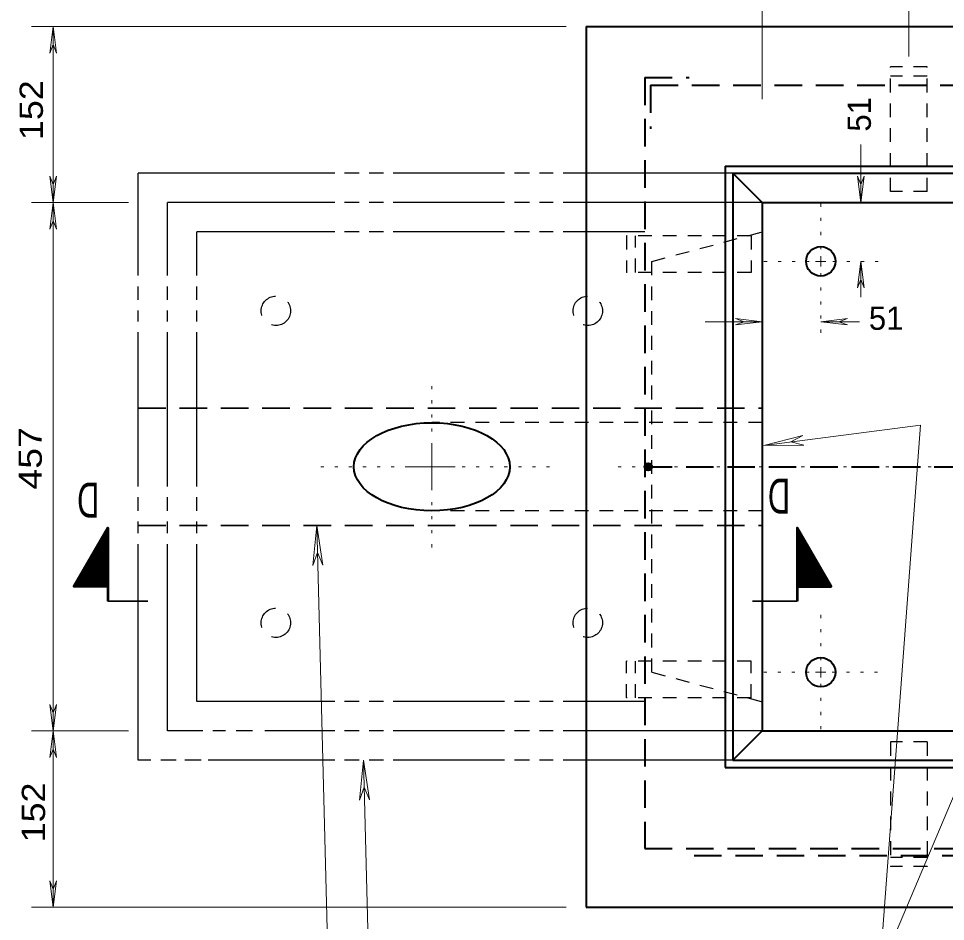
# Model space of a CAD drawing. Extents: x 312583 to 312854, y 144419 to 144597.
# Drawn here: x 312621.2 to 312651.47, y 144539.73 to 144569.21 of the extents above; entities that cross this region are included whole.
import ezdxf
from ezdxf.enums import TextEntityAlignment as Align

# ---------------------------------------------------------------- set-up
doc = ezdxf.new("R2010")
doc.units = 0
doc.header["$LTSCALE"] = 0.3
for name, pattern in [('DOTTED', [1.5, 0.3, -1.2]), ('MEDIUM_DASHED', [4.5, 3, -1.5]), ('SHORT_DASHED', [2.7, 1.5, -1.2])]:
    doc.linetypes.add(name, pattern=pattern)
doc.layers.add('1', color=7, linetype='Continuous', lineweight=25)
doc.layers.add('2', color=7, linetype='Continuous', lineweight=13)

msp = doc.modelspace()

# ---------------------------------------------------------------- linework, layer by layer
at = {"layer": '1', "lineweight": 40}
for p, q in [((312639.7337, 144568.9533), (312685.7337, 144568.9533)), ((312639.7337, 144568.9533), (312639.7337, 144540.2033)), ((312644.28, 144564.3993), (312644.28, 144544.7573)), ((312644.5254, 144564.1616), (312644.5254, 144544.995)), ((312644.5254, 144564.1616), (312645.4837, 144563.2033)), ((312645.4837, 144563.2033), (312666.659, 144563.2033)), ((312645.4837, 144545.9533), (312644.5254, 144544.995)), ((312645.4837, 144545.9533), (312644.5254, 144544.995)), ((312644.5254, 144544.995), (312680.942, 144544.995)), ((312644.28, 144544.7573), (312681.1797, 144544.7573)), ((312639.7337, 144540.2033), (312653.1504, 144540.2033))]:
    msp.add_line(p, q, dxfattribs=at)
at = {"layer": '1', "linetype": 'SHORT_DASHED'}
for p, q in [((312650.8734, 144567.6346), (312649.6774, 144567.6346)), ((312649.6774, 144563.5636), (312649.6774, 144567.6346)), ((312650.8734, 144563.5636), (312650.8734, 144567.6346)), ((312650.8734, 144567.3356), (312649.6774, 144567.3356)), ((312650.8734, 144563.5636), (312649.6774, 144563.5636)), ((312641.0524, 144562.1223), (312641.0524, 144560.9263)), ((312645.1234, 144562.1223), (312641.0524, 144562.1223)), ((312641.3514, 144560.9263), (312641.3514, 144562.1223)), ((312641.888, 144561.2866), (312645.4837, 144562.245)), ((312645.1234, 144562.1223), (312645.1234, 144560.9263)), ((312641.888, 144547.87), (312641.888, 144561.2866)), ((312645.1234, 144560.9263), (312641.0524, 144560.9263)), ((312645.4837, 144556.0196), (312634.7044, 144556.0196)), ((312645.4837, 144553.1446), (312634.6967, 144553.1446)), ((312641.0524, 144547.0343), (312641.0524, 144548.2303)), ((312645.1234, 144548.2303), (312641.0524, 144548.2303)), ((312641.3514, 144547.0343), (312641.3514, 144548.2303)), ((312645.1234, 144547.0343), (312645.1234, 144548.2303)), ((312641.888, 144547.87), (312645.4837, 144546.9116)), ((312645.1234, 144547.0343), (312641.0524, 144547.0343)), ((312650.8734, 144545.593), (312649.6774, 144545.593)), ((312649.6774, 144545.593), (312649.6774, 144541.5296)), ((312650.8734, 144545.593), (312650.8734, 144541.5296)), ((312650.8734, 144541.821), (312649.6774, 144541.821)), ((312650.8734, 144541.5296), (312649.6774, 144541.5296))]:
    msp.add_line(p, q, dxfattribs=at)
at = {"layer": '1', "linetype": 'MEDIUM_DASHED', "lineweight": 40}
for p, q in [((312641.6504, 144567.2896), (312641.6504, 144542.12)), ((312641.6504, 144567.2896), (312643.0994, 144567.2896)), ((312641.842, 144567.0366), (312641.842, 144565.6106)), ((312641.6504, 144554.5783), (312656.9837, 144554.5783)), ((312641.6504, 144542.12), (312683.817, 144542.12)), ((312643.2604, 144541.8823), (312655.067, 144541.8823))]:
    msp.add_line(p, q, dxfattribs=at)
at = {"layer": '1'}
for p, q in [((312631.5304, 144564.1616), (312625.1134, 144564.1616)), ((312625.1134, 144560.819), (312625.1134, 144564.1616)), ((312632.3277, 144564.1616), (312631.8524, 144564.1616)), ((312633.1174, 144564.1616), (312632.6497, 144564.1616)), ((312637.0734, 144564.1616), (312633.4394, 144564.1616)), ((312637.8937, 144564.1616), (312637.3954, 144564.1616)), ((312638.6604, 144564.1616), (312638.2157, 144564.1616)), ((312644.5254, 144564.1616), (312638.9824, 144564.1616)), ((312631.5304, 144563.2033), (312626.0717, 144563.2033)), ((312626.0717, 144560.819), (312626.0717, 144563.2033)), ((312632.3277, 144563.2033), (312631.8524, 144563.2033)), ((312633.1174, 144563.2033), (312632.6497, 144563.2033)), ((312637.0734, 144563.2033), (312633.4394, 144563.2033)), ((312637.8937, 144563.2033), (312637.3954, 144563.2033)), ((312638.6604, 144563.2033), (312638.2157, 144563.2033)), ((312645.4837, 144563.2033), (312638.9824, 144563.2033)), ((312631.5304, 144562.245), (312627.03, 144562.245)), ((312627.03, 144560.819), (312627.03, 144562.245)), ((312632.3277, 144562.245), (312631.8524, 144562.245)), ((312633.1174, 144562.245), (312632.6497, 144562.245)), ((312637.0734, 144562.245), (312633.4394, 144562.245)), ((312637.8937, 144562.245), (312637.3954, 144562.245)), ((312638.6604, 144562.245), (312638.2157, 144562.245)), ((312641.6504, 144562.245), (312638.9824, 144562.245)), ((312625.1134, 144560.0293), (312625.1134, 144560.4663)), ((312626.0717, 144560.0293), (312626.0717, 144560.4663)), ((312627.03, 144560.0293), (312627.03, 144560.4663)), ((312625.1134, 144559.324), (312625.1134, 144559.6766)), ((312626.0717, 144559.324), (312626.0717, 144559.6766)), ((312627.03, 144559.324), (312627.03, 144559.6766)), ((312625.1134, 144553.9343), (312625.1134, 144558.9713)), ((312626.0717, 144553.9343), (312626.0717, 144558.9713)), ((312627.03, 144553.9343), (312627.03, 144558.9713)), ((312625.1134, 144553.1446), (312625.1134, 144553.5816)), ((312626.0717, 144553.1446), (312626.0717, 144553.5816)), ((312627.03, 144553.1446), (312627.03, 144553.5816)), ((312625.1134, 144552.4086), (312625.1134, 144552.792)), ((312626.0717, 144552.4086), (312626.0717, 144552.792)), ((312627.03, 144552.4086), (312627.03, 144552.792)), ((312625.1134, 144544.995), (312625.1134, 144552.056)), ((312626.0717, 144545.9533), (312626.0717, 144552.056)), ((312627.03, 144546.9116), (312627.03, 144552.056)), ((312631.5304, 144546.9116), (312627.03, 144546.9116)), ((312632.3277, 144546.9116), (312631.8524, 144546.9116)), ((312633.1174, 144546.9116), (312632.6497, 144546.9116)), ((312637.0734, 144546.9116), (312633.4394, 144546.9116)), ((312637.8937, 144546.9116), (312637.3954, 144546.9116)), ((312638.6604, 144546.9116), (312638.2157, 144546.9116)), ((312641.6504, 144546.9116), (312638.9824, 144546.9116)), ((312627.2217, 144545.9533), (312626.0717, 144545.9533)), ((312627.9577, 144545.9533), (312627.5437, 144545.9533)), ((312628.8394, 144545.9533), (312628.3104, 144545.9533)), ((312631.5304, 144545.9533), (312629.2457, 144545.9533)), ((312632.3277, 144545.9533), (312631.8524, 144545.9533)), ((312633.1174, 144545.9533), (312632.6497, 144545.9533)), ((312637.0734, 144545.9533), (312633.4394, 144545.9533)), ((312637.8937, 144545.9533), (312637.3954, 144545.9533)), ((312638.6604, 144545.9533), (312638.2157, 144545.9533)), ((312645.4837, 144545.9533), (312638.9824, 144545.9533)), ((312625.5274, 144544.995), (312625.1134, 144544.995)), ((312626.3477, 144544.995), (312625.8494, 144544.995)), ((312627.168, 144544.995), (312626.639, 144544.995)), ((312631.5304, 144544.995), (312627.398, 144544.995)), ((312632.3277, 144544.995), (312631.8524, 144544.995)), ((312633.1174, 144544.995), (312632.6497, 144544.995)), ((312637.0734, 144544.995), (312633.4394, 144544.995)), ((312637.8937, 144544.995), (312637.3954, 144544.995)), ((312638.6604, 144544.995), (312638.2157, 144544.995)), ((312644.5254, 144544.995), (312638.9824, 144544.995))]:
    msp.add_line(p, q, dxfattribs=at)
at = {"layer": '1', "linetype": 'DOTTED', "lineweight": 13}
for p, q in [((312634.6967, 144555.7283), (312634.6967, 144557.5376)), ((312633.93, 144554.5783), (312630.8557, 144554.5783)), ((312638.5454, 144554.5783), (312635.4634, 144554.5783)), ((312634.6967, 144553.4283), (312634.6967, 144551.6266))]:
    msp.add_line(p, q, dxfattribs=at)
at = {"layer": '1', "linetype": 'MEDIUM_DASHED', "lineweight": 35}
for p, q in [((312625.1134, 144556.495), (312645.4837, 144556.495)), ((312625.1134, 144552.6616), (312645.4837, 144552.6616))]:
    msp.add_line(p, q, dxfattribs=at)
at = {"layer": '1', "lineweight": 13}
for q in [(312634.6967, 144555.345), (312633.93, 144554.5783), (312634.6967, 144553.8116), (312635.4634, 144554.5783)]:
    msp.add_line((312634.6967, 144554.5783), q, dxfattribs=at)
at = {"layer": '1', "lineweight": 35}
for p, q in [((312624.1244, 144552.3396), (312624.017, 144552.4086)), ((312624.1244, 144552.3703), (312624.0324, 144552.424)), ((312624.1244, 144552.401), (312624.04, 144552.447)), ((312624.1244, 144552.4316), (312624.0554, 144552.47)), ((312624.1244, 144552.4546), (312624.063, 144552.4853)), ((312624.1244, 144552.4853), (312624.0784, 144552.5083)), ((312624.1244, 144552.5083), (312624.086, 144552.5313)), ((312624.1244, 144552.539), (312624.1014, 144552.5466)), ((312624.1244, 144552.5696), (312624.109, 144552.5696)), ((312646.626, 144552.5696), (312646.6414, 144552.5696)), ((312646.626, 144552.539), (312646.649, 144552.5466)), ((312646.626, 144552.5083), (312646.6644, 144552.5313)), ((312646.626, 144552.4853), (312646.672, 144552.5083)), ((312646.626, 144552.4546), (312646.6874, 144552.4853)), ((312646.626, 144552.4316), (312646.695, 144552.47)), ((312646.626, 144552.401), (312646.7104, 144552.447)), ((312646.626, 144552.3703), (312646.718, 144552.424)), ((312646.626, 144552.3396), (312646.7334, 144552.4086)), ((312624.1244, 144551.9333), (312623.8407, 144552.0943)), ((312624.1244, 144551.9563), (312623.8484, 144552.1096)), ((312624.1244, 144551.987), (312623.8637, 144552.1403)), ((312624.1244, 144552.01), (312623.8714, 144552.1556)), ((312624.1244, 144552.0406), (312623.8867, 144552.1786)), ((312624.1244, 144552.0713), (312623.8944, 144552.2016)), ((312624.1244, 144552.0943), (312623.9097, 144552.217)), ((312624.1244, 144552.125), (312623.9174, 144552.24)), ((312624.1244, 144552.148), (312623.9327, 144552.263)), ((312624.1244, 144552.1786), (312623.948, 144552.2783)), ((312624.1244, 144552.2093), (312623.9557, 144552.3013)), ((312624.1244, 144552.24), (312623.971, 144552.3243)), ((312624.1244, 144552.263), (312623.9864, 144552.3396)), ((312624.1244, 144552.2936), (312623.994, 144552.3626)), ((312624.1244, 144552.3166), (312624.0094, 144552.3856)), ((312646.626, 144552.3166), (312646.741, 144552.3856)), ((312646.626, 144552.2936), (312646.7564, 144552.3626)), ((312646.626, 144552.263), (312646.764, 144552.3396)), ((312646.626, 144552.24), (312646.7794, 144552.3243)), ((312646.626, 144552.2093), (312646.7947, 144552.3013)), ((312646.626, 144552.1786), (312646.8024, 144552.2783)), ((312646.626, 144552.148), (312646.8177, 144552.263)), ((312646.626, 144552.125), (312646.833, 144552.24)), ((312646.626, 144552.0943), (312646.8407, 144552.217)), ((312646.626, 144552.0713), (312646.856, 144552.2016)), ((312646.626, 144552.0406), (312646.8637, 144552.1786)), ((312646.626, 144552.01), (312646.879, 144552.1556)), ((312646.626, 144551.987), (312646.8867, 144552.1403)), ((312646.626, 144551.9563), (312646.902, 144552.1096)), ((312646.626, 144551.9333), (312646.9097, 144552.0943)), ((312624.1244, 144551.5423), (312623.672, 144551.803)), ((312624.1244, 144551.573), (312623.6797, 144551.826)), ((312624.1244, 144551.6036), (312623.695, 144551.8413)), ((312624.1244, 144551.6266), (312623.7027, 144551.8643)), ((312624.1244, 144551.6496), (312623.718, 144551.8873)), ((312624.1244, 144551.6803), (312623.7257, 144551.9103)), ((312624.1244, 144551.711), (312623.741, 144551.9256)), ((312624.1244, 144551.7416), (312623.7564, 144551.9486)), ((312624.1244, 144551.7646), (312623.764, 144551.9716)), ((312624.1244, 144551.7953), (312623.7794, 144551.987)), ((312624.1244, 144551.8183), (312623.7947, 144552.01)), ((312624.1244, 144551.849), (312623.8024, 144552.033)), ((312624.1244, 144551.872), (312623.8177, 144552.0483)), ((312624.1244, 144551.9026), (312623.8254, 144552.0713)), ((312646.626, 144551.9026), (312646.925, 144552.0713)), ((312646.626, 144551.872), (312646.9327, 144552.0483)), ((312646.626, 144551.849), (312646.948, 144552.033)), ((312646.626, 144551.8183), (312646.9557, 144552.01)), ((312646.626, 144551.7953), (312646.971, 144551.987)), ((312646.626, 144551.7646), (312646.9864, 144551.9716)), ((312646.626, 144551.7416), (312646.994, 144551.9486)), ((312646.626, 144551.711), (312647.0094, 144551.9256)), ((312646.626, 144551.6803), (312647.0247, 144551.9103)), ((312646.626, 144551.6496), (312647.0324, 144551.8873)), ((312646.626, 144551.6266), (312647.0477, 144551.8643)), ((312646.626, 144551.6036), (312647.0554, 144551.8413)), ((312646.626, 144551.573), (312647.0707, 144551.826)), ((312646.626, 144551.5423), (312647.0784, 144551.803)), ((312624.1244, 144551.1283), (312623.4957, 144551.4886)), ((312624.1244, 144551.1513), (312623.5034, 144551.5116)), ((312624.1244, 144551.182), (312623.5187, 144551.5346)), ((312624.1244, 144551.2126), (312623.5264, 144551.55)), ((312624.1244, 144551.2433), (312623.5417, 144551.573)), ((312624.1244, 144551.2663), (312623.5494, 144551.596)), ((312624.1244, 144551.297), (312623.5647, 144551.6113)), ((312624.1167, 144551.32), (312623.5724, 144551.642)), ((312624.1244, 144551.3506), (312623.5877, 144551.6573)), ((312624.1244, 144551.3736), (312623.603, 144551.6803)), ((312624.1244, 144551.4043), (312623.6107, 144551.7033)), ((312624.1244, 144551.435), (312623.626, 144551.7186)), ((312624.1244, 144551.458), (312623.6337, 144551.7416)), ((312624.1244, 144551.4886), (312623.649, 144551.7646)), ((312624.1244, 144551.5193), (312623.6567, 144551.78)), ((312646.626, 144551.5193), (312647.0937, 144551.78)), ((312646.626, 144551.4886), (312647.1014, 144551.7646)), ((312646.626, 144551.458), (312647.1167, 144551.7416)), ((312646.626, 144551.435), (312647.1244, 144551.7186)), ((312646.626, 144551.4043), (312647.1397, 144551.7033)), ((312646.626, 144551.3736), (312647.1474, 144551.6803)), ((312646.626, 144551.3506), (312647.1627, 144551.6573)), ((312646.626, 144551.297), (312647.1857, 144551.6113)), ((312646.626, 144551.2663), (312647.201, 144551.596)), ((312646.626, 144551.2433), (312647.2087, 144551.573)), ((312646.626, 144551.2126), (312647.224, 144551.55)), ((312646.626, 144551.182), (312647.2317, 144551.5346)), ((312646.626, 144551.1513), (312647.247, 144551.5116)), ((312646.626, 144551.1283), (312647.2547, 144551.4886)), ((312646.6337, 144551.32), (312647.178, 144551.642)), ((312624.1244, 144550.7143), (312623.3117, 144551.182)), ((312624.1244, 144550.745), (312623.327, 144551.205)), ((312624.1244, 144550.768), (312623.3347, 144551.2203)), ((312624.1244, 144550.7986), (312623.35, 144551.2433)), ((312624.1167, 144550.8216), (312623.3577, 144551.2663)), ((312624.1167, 144550.8523), (312623.373, 144551.2816)), ((312624.1244, 144550.8753), (312623.3807, 144551.3046)), ((312624.1244, 144550.906), (312623.396, 144551.3276)), ((312624.1244, 144550.9366), (312623.4114, 144551.343)), ((312624.1244, 144550.9596), (312623.419, 144551.366)), ((312624.1244, 144550.9903), (312623.4344, 144551.389)), ((312624.1244, 144551.021), (312623.4497, 144551.412)), ((312624.1244, 144551.044), (312623.4574, 144551.4273)), ((312624.1167, 144551.0746), (312623.4727, 144551.4503)), ((312624.1244, 144551.1053), (312623.4804, 144551.4733)), ((312646.626, 144551.1053), (312647.27, 144551.4733)), ((312646.626, 144551.044), (312647.293, 144551.4273)), ((312646.626, 144551.021), (312647.3007, 144551.412)), ((312646.626, 144550.9903), (312647.316, 144551.389)), ((312646.626, 144550.9596), (312647.3314, 144551.366)), ((312646.626, 144550.9366), (312647.339, 144551.343)), ((312646.626, 144550.906), (312647.3544, 144551.3276)), ((312646.626, 144550.8753), (312647.3697, 144551.3046)), ((312646.626, 144550.7986), (312647.4004, 144551.2433)), ((312646.626, 144550.768), (312647.4157, 144551.2203)), ((312646.626, 144550.745), (312647.4234, 144551.205)), ((312646.626, 144550.7143), (312647.4387, 144551.182)), ((312646.6337, 144551.0746), (312647.2777, 144551.4503)), ((312646.6337, 144550.8523), (312647.3774, 144551.2816)), ((312646.6337, 144550.8216), (312647.3927, 144551.2663)), ((312623.4727, 144550.6683), (312623.1354, 144550.8753)), ((312623.5264, 144550.6683), (312623.143, 144550.8906)), ((312623.5724, 144550.6683), (312623.1584, 144550.9136)), ((312623.6184, 144550.6683), (312623.166, 144550.9366)), ((312623.672, 144550.6683), (312623.1814, 144550.952)), ((312623.718, 144550.6683), (312623.189, 144550.975)), ((312623.764, 144550.6683), (312623.2044, 144550.9903)), ((312623.8177, 144550.6683), (312623.2197, 144551.0133)), ((312623.8637, 144550.6683), (312623.2274, 144551.0363)), ((312623.9097, 144550.6683), (312623.2427, 144551.0516)), ((312623.9557, 144550.6683), (312623.258, 144551.0746)), ((312624.0094, 144550.6683), (312623.2657, 144551.0976)), ((312624.0477, 144550.6683), (312623.281, 144551.113)), ((312624.1014, 144550.6683), (312623.2887, 144551.1436)), ((312624.1244, 144550.6836), (312623.304, 144551.159)), ((312646.626, 144550.6836), (312647.4464, 144551.159)), ((312646.649, 144550.6683), (312647.4617, 144551.1436)), ((312646.7027, 144550.6683), (312647.4694, 144551.113)), ((312646.741, 144550.6683), (312647.4847, 144551.0976)), ((312646.7947, 144550.6683), (312647.4924, 144551.0746)), ((312646.8407, 144550.6683), (312647.5077, 144551.0516)), ((312646.8867, 144550.6683), (312647.523, 144551.0363)), ((312646.9327, 144550.6683), (312647.5307, 144551.0133)), ((312646.9864, 144550.6683), (312647.546, 144550.9903)), ((312647.0324, 144550.6683), (312647.5614, 144550.975)), ((312647.0784, 144550.6683), (312647.569, 144550.952)), ((312647.132, 144550.6683), (312647.5844, 144550.9366)), ((312647.178, 144550.6683), (312647.592, 144550.9136)), ((312647.224, 144550.6683), (312647.6074, 144550.8906)), ((312647.2777, 144550.6683), (312647.615, 144550.8753)), ((312623.0434, 144550.6683), (312623.028, 144550.6836)), ((312623.0894, 144550.6683), (312623.0357, 144550.7066)), ((312623.143, 144550.6683), (312623.051, 144550.722)), ((312623.189, 144550.6683), (312623.0664, 144550.745)), ((312623.2427, 144550.6683), (312623.074, 144550.768)), ((312623.281, 144550.6683), (312623.0894, 144550.7833)), ((312623.3347, 144550.6683), (312623.097, 144550.8063)), ((312623.3807, 144550.6683), (312623.1124, 144550.8293)), ((312623.4267, 144550.6683), (312623.12, 144550.8446)), ((312647.3237, 144550.6683), (312647.6304, 144550.8446)), ((312647.3697, 144550.6683), (312647.638, 144550.8293)), ((312647.4157, 144550.6683), (312647.6534, 144550.8063)), ((312647.4694, 144550.6683), (312647.661, 144550.7833)), ((312647.5077, 144550.6683), (312647.6764, 144550.768)), ((312647.5614, 144550.6683), (312647.684, 144550.745)), ((312647.6074, 144550.6683), (312647.6994, 144550.722)), ((312647.661, 144550.6683), (312647.7147, 144550.7066)), ((312647.707, 144550.6683), (312647.7224, 144550.6836)), ((312624.1244, 144550.193), (312625.4277, 144550.193)), ((312645.1694, 144550.193), (312646.626, 144550.193))]:
    msp.add_line(p, q, dxfattribs=at)
at = {"layer": '1', "lineweight": 53}
for p, q in [((312624.1244, 144550.6683), (312624.1244, 144550.193)), ((312646.626, 144550.6683), (312646.626, 144550.193))]:
    msp.add_line(p, q, dxfattribs=at)
at = {"layer": '1', "linetype": 'MEDIUM_DASHED', "lineweight": 40}
msp.add_lwpolyline([(312641.842, 144567.0366), (312683.817, 144567.0366), (312683.817, 144542.12)], dxfattribs=at)
at = {"layer": '1', "lineweight": 40}
for points in [[(312644.28, 144564.3993), (312681.1797, 144564.3993), (312681.1797, 144544.7573)], [(312644.5254, 144564.1616), (312680.942, 144564.1616), (312680.942, 144544.995)], [(312645.4837, 144563.2033), (312645.4837, 144545.9533), (312679.9837, 144545.9533)]]:
    msp.add_lwpolyline(points, dxfattribs=at)
at = {"layer": '1', "lineweight": 53}
for points in [[(312624.1244, 144550.6683), (312623.0127, 144550.6683), (312624.1244, 144552.585)], [(312646.626, 144550.6683), (312647.7377, 144550.6683), (312646.626, 144552.585)]]:
    msp.add_lwpolyline(points, close=True, dxfattribs=at)
at = {"layer": '1', "lineweight": 40}
for centre, radius in [((312647.3975, 144561.2866), 0.4792), ((312641.7673, 144554.5783), 0.1198), ((312641.7673, 144554.5783), 0.0838), ((312641.7673, 144554.5783), 0.0587), ((312647.3975, 144547.87), 0.4792)]:
    msp.add_circle(centre, radius, dxfattribs=at)
at = {"layer": '1', "linetype": 'MEDIUM_DASHED'}
for centre in [(312629.6079, 144559.6699), (312639.7912, 144559.6699), (312629.6079, 144549.4867), (312639.7912, 144549.4867)]:
    msp.add_circle(centre, 0.4792, dxfattribs=at)
at = {"layer": '1', "lineweight": 40}
msp.add_ellipse((312634.7001, 144554.5783), major_axis=(-2.5458, 0), ratio=0.564653, dxfattribs=at)
at = {"layer": '2'}
for p, q in [((312645.4837, 144566.5843), (312645.4837, 144572.0813)), ((312650.2754, 144567.972), (312650.2754, 144572.0813)), ((312639.082, 144568.9533), (312621.6327, 144568.9533)), ((312622.338, 144568.9533), (312622.2307, 144568.087)), ((312622.338, 144568.9533), (312622.4454, 144568.087)), ((312622.2307, 144568.087), (312622.338, 144568.363)), ((312622.4454, 144568.087), (312622.338, 144568.363)), ((312648.7037, 144563.2033), (312648.7037, 144565.097)), ((312622.2307, 144564.0696), (312622.338, 144563.7936)), ((312622.338, 144563.2033), (312622.2307, 144564.0696)), ((312622.4454, 144564.0696), (312622.338, 144563.7936)), ((312622.338, 144563.2033), (312622.4454, 144564.0696)), ((312648.5964, 144564.0696), (312648.7037, 144563.7936)), ((312648.7037, 144563.2033), (312648.5964, 144564.0696)), ((312648.811, 144564.0696), (312648.7037, 144563.7936)), ((312648.7037, 144563.2033), (312648.811, 144564.0696)), ((312624.7914, 144563.2033), (312621.6327, 144563.2033)), ((312622.338, 144563.2033), (312622.2307, 144562.337)), ((312622.338, 144563.2033), (312622.4454, 144562.337)), ((312659.9354, 144563.2033), (312649.317, 144538.118)), ((312622.2307, 144562.337), (312622.338, 144562.613)), ((312622.4454, 144562.337), (312622.338, 144562.613)), ((312647.4004, 144561.2866), (312647.224, 144561.2866)), ((312647.4004, 144561.2866), (312647.4004, 144561.4553)), ((312647.4004, 144561.2866), (312647.569, 144561.2866)), ((312647.4004, 144561.2866), (312647.4004, 144561.118)), ((312648.7037, 144561.2866), (312648.5964, 144560.4203)), ((312648.7037, 144560.1136), (312648.7037, 144561.2866)), ((312648.7037, 144561.2866), (312648.811, 144560.4203)), ((312648.5964, 144560.4203), (312648.7037, 144560.6963)), ((312648.811, 144560.4203), (312648.7037, 144560.6963)), ((312644.6174, 144559.4236), (312644.8934, 144559.3163)), ((312645.4837, 144559.3163), (312644.6174, 144559.4236)), ((312647.4004, 144559.3163), (312648.2667, 144559.4236)), ((312648.2667, 144559.4236), (312647.9907, 144559.3163)), ((312643.6207, 144559.3163), (312645.4837, 144559.3163)), ((312644.6174, 144559.209), (312644.8934, 144559.3163)), ((312645.4837, 144559.3163), (312644.6174, 144559.209)), ((312647.4004, 144559.3163), (312648.6654, 144559.3163)), ((312647.4004, 144559.3163), (312648.2667, 144559.209)), ((312648.2667, 144559.209), (312647.9907, 144559.3163)), ((312645.5374, 144555.276), (312650.651, 144555.9353)), ((312650.651, 144555.9353), (312649.317, 144538.118)), ((312645.5374, 144555.276), (312646.81, 144555.598)), ((312646.81, 144555.598), (312646.419, 144555.391)), ((312645.5374, 144555.276), (312646.8484, 144555.2836)), ((312646.8484, 144555.2836), (312646.419, 144555.391)), ((312630.9477, 144552.6616), (312630.8174, 144551.3583)), ((312630.9477, 144552.6616), (312631.5917, 144527.5916)), ((312630.9477, 144552.6616), (312631.1394, 144551.366)), ((312630.8174, 144551.3583), (312630.9707, 144551.78)), ((312631.1394, 144551.366), (312630.9707, 144551.78)), ((312647.4004, 144547.87), (312647.224, 144547.87)), ((312647.4004, 144547.87), (312647.4004, 144548.0386)), ((312647.4004, 144547.87), (312647.569, 144547.87)), ((312647.4004, 144547.87), (312647.4004, 144547.7013)), ((312622.2307, 144546.8196), (312622.338, 144546.5436)), ((312622.338, 144545.9533), (312622.2307, 144546.8196)), ((312622.4454, 144546.8196), (312622.338, 144546.5436)), ((312622.338, 144545.9533), (312622.4454, 144546.8196)), ((312624.7914, 144545.9533), (312621.6327, 144545.9533)), ((312622.338, 144545.9533), (312622.2307, 144545.087)), ((312622.338, 144545.9533), (312622.4454, 144545.087)), ((312622.2307, 144545.087), (312622.338, 144545.363)), ((312622.4454, 144545.087), (312622.338, 144545.363)), ((312632.4657, 144544.995), (312632.343, 144543.6916)), ((312632.4657, 144544.995), (312632.7264, 144534.99)), ((312632.4657, 144544.995), (312632.665, 144543.6993)), ((312632.343, 144543.6916), (312632.4887, 144544.1133)), ((312632.665, 144543.6993), (312632.4887, 144544.1133)), ((312622.2307, 144541.062), (312622.338, 144540.786)), ((312622.338, 144540.1956), (312622.2307, 144541.062)), ((312622.4454, 144541.062), (312622.338, 144540.786)), ((312622.338, 144540.1956), (312622.4454, 144541.062)), ((312639.082, 144540.2033), (312621.6327, 144540.2033))]:
    msp.add_line(p, q, dxfattribs=at)
at = {"layer": '2', "linetype": 'DOTTED'}
for p, q in [((312647.4004, 144561.6853), (312647.4004, 144563.257)), ((312647.0247, 144561.2866), (312645.43, 144561.2866)), ((312647.7914, 144561.2866), (312649.363, 144561.2866)), ((312647.4004, 144560.8956), (312647.4004, 144558.6646)), ((312661.5837, 144554.5783), (312640.4314, 144554.5783)), ((312647.4004, 144548.261), (312647.4004, 144549.8403)), ((312647.017, 144547.87), (312645.43, 144547.87)), ((312647.776, 144547.87), (312649.363, 144547.87)), ((312647.4004, 144547.4943), (312647.4004, 144545.8996))]:
    msp.add_line(p, q, dxfattribs=at)
at = {"layer": '2'}
msp.add_lwpolyline([(312622.338, 144540.1956), (312622.338, 144545.9533), (312622.338, 144563.2033), (312622.338, 144568.9533)], dxfattribs=at)

# ---------------------------------------------------------------- texts
at = {"layer": '1', "width": 0.65}
for p in [(312623.4803, 144554.0646), (312646.0358, 144554.195)]:
    msp.add_text('D', height=1.15, rotation=180, dxfattribs=at).set_placement(p, align=Align.CENTER)
at = {"layer": '2'}
for s, width, p in [('152 ', 1.15, (312622.0002, 144565.2474)), ('457 ', 1.2, (312621.9648, 144553.8363)), ('152 ', 1.15, (312622.0711, 144542.3182))]:
    msp.add_text(s, height=0.76, rotation=90, dxfattribs=dict(at, width=width)).set_placement(p)
msp.add_text('51 ', height=0.76, rotation=90, dxfattribs=at).set_placement((312649.0346, 144565.521))
msp.add_text('51 ', height=0.76, dxfattribs=at).set_placement((312648.9682, 144559.0509))

doc.saveas('drawing.dxf')
